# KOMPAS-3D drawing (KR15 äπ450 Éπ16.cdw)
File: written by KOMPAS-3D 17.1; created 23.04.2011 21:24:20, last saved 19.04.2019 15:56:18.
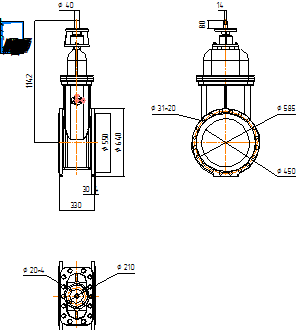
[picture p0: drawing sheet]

Sheet 1: A4, portrait

Title block, sheet 1: name: KR15 Ду450 Ру16; material: Внимание! Данный продукт является объектом авторского права ООО «Торговый Дом АДЛ». / Запрещается изменение, копирование, распространение / (в том числе путем копирования на другие сайты и ресурсы в Интернете) / или любое иное использование информации и объектов без предварительного / согласия правообладателя (ООО «Торговый Дом АДЛ»).; scale: 1:1; sheets: 1; organisation: ООО "Торговый дом АДЛ"; sheet format: A4; stored path: \\adlc.lan\data\АДЛ_ПКД\3D-модели\ADL production\Клиновые задвижки серии KR ГРАНАР\Клиновые задвижки KR15\С голым штоком\KOMPAS 2D\KR15 Ду450 Ру16.cdw

Views: Спереди 1, Проекционный вид 2, Проекционный вид 3
Dimensions and other numbers on the sheet: 450; 585; 31; 550; 640; 14; 40; 80; 1142; 210; 20; 330; 30; 4; 1:1; 1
